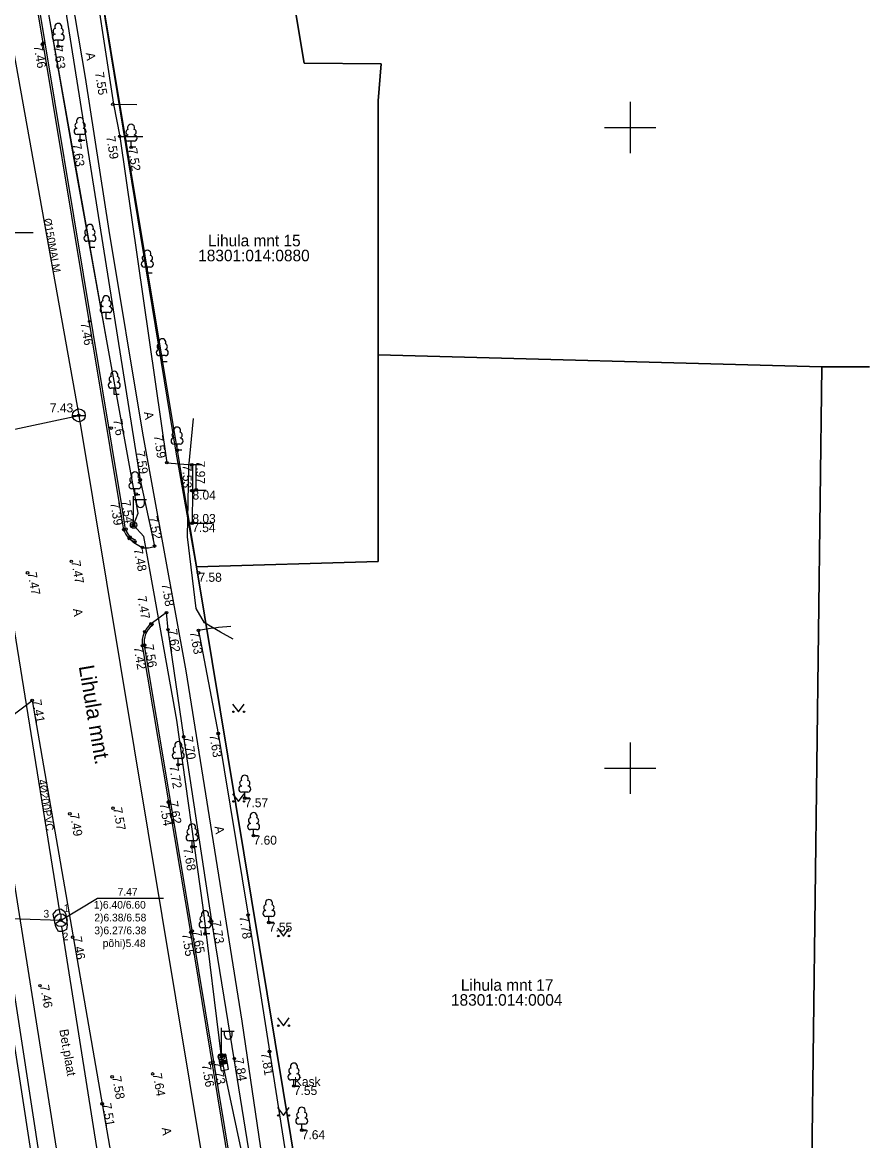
# Model space of a CAD drawing. Extents: x 473307 to 473719, y 6532843 to 6533381.
# Drawn here: x 473652.6 to 473718.7, y 6532970.9 to 6533058.2 of the extents above; entities that cross this region are included whole.
import ezdxf

# ---------------------------------------------------------------- set-up
doc = ezdxf.new("R2010")
doc.units = 0
for name, color, linetype in [('Default', 7, 'Continuous'), ('ELRAJATISMP', 7, 'Continuous'), ('HALJASTUS', 7, 'Continuous'), ('HOONEDET', 7, 'Continuous'), ('KORGUS', 7, 'Continuous'), ('KPKAABEL', 7, 'Continuous'), ('MPKAABEL', 7, 'Continuous'), ('PIIR', 7, 'Continuous'), ('POST', 7, 'Continuous'), ('PUU', 7, 'Continuous'), ('SIKAEV', 7, 'Continuous'), ('SIKAEV_NR', 7, 'Continuous'), ('SITRASS', 7, 'Continuous'), ('SITRASS_TEKST', 7, 'Continuous'), ('TEE', 7, 'Continuous'), ('TRUUP', 7, 'Continuous'), ('TTRASS', 7, 'Continuous'), ('VKAEV', 7, 'Continuous'), ('VORK', 7, 'Continuous'), ('VTRASS', 7, 'Continuous')]:
    doc.layers.add(name, color=color, linetype=linetype)

# ---------------------------------------------------------------- blocks, each defined once
blk = doc.blocks.new('eljk')
at = {"layer": 'Default'}
for p, q in [((1.19, 0.6), (-1.19, 0.6)), ((-1.19, 0.6), (-1.19, -0.6)), ((-0.27, 0.6), (-0.27, -0.6)), ((0.27, 0.57), (-0.27, 0.57)), ((0.27, 0.54), (-0.27, 0.54)), ((0.27, 0.51), (-0.27, 0.51)), ((0.27, 0.49), (-0.27, 0.49)), ((0.27, 0.46), (-0.27, 0.46)), ((0.27, 0.43), (-0.27, 0.43)), ((0.27, 0.4), (-0.27, 0.4)), ((0.27, 0.37), (-0.27, 0.37)), ((0.27, 0.34), (-0.27, 0.34)), ((0.27, 0.31), (-0.27, 0.31)), ((0.27, 0.28), (-0.27, 0.28)), ((0.27, 0.25), (-0.27, 0.25)), ((0.27, 0.22), (-0.27, 0.22)), ((0.27, 0.2), (-0.27, 0.2)), ((0.27, 0.17), (-0.27, 0.17)), ((0.27, 0.14), (-0.27, 0.14)), ((0.27, 0.11), (-0.27, 0.11)), ((0.27, 0.09), (-0.27, 0.09)), ((0.27, 0.06), (-0.27, 0.06)), ((0.27, 0.03), (-0.27, 0.03)), ((0.27, 0.6), (0.27, -0.6)), ((1.19, -0.6), (1.19, 0.6)), ((-1.19, -0.6), (1.19, -0.6)), ((0.27, 0), (-0.27, 0)), ((0.27, -0.03), (-0.27, -0.03)), ((0.27, -0.06), (-0.27, -0.06)), ((0.27, -0.09), (-0.27, -0.09)), ((0.27, -0.12), (-0.27, -0.12)), ((0.27, -0.14), (-0.27, -0.14)), ((0.27, -0.17), (-0.27, -0.17)), ((0.27, -0.2), (-0.27, -0.2)), ((0.27, -0.23), (-0.27, -0.23)), ((0.27, -0.26), (-0.27, -0.26)), ((0.27, -0.29), (-0.27, -0.29)), ((0.27, -0.32), (-0.27, -0.32)), ((0.27, -0.35), (-0.27, -0.35)), ((0.27, -0.37), (-0.27, -0.37)), ((0.27, -0.4), (-0.27, -0.4)), ((0.27, -0.43), (-0.27, -0.43)), ((0.27, -0.46), (-0.27, -0.46)), ((0.27, -0.48), (-0.27, -0.48)), ((0.27, -0.51), (-0.27, -0.51)), ((0.27, -0.54), (-0.27, -0.54)), ((0.27, -0.57), (-0.27, -0.57))]:
    blk.add_line(p, q, dxfattribs=at)
blk = doc.blocks.new('LEHTP1')
at = {"layer": 'Default'}
for p, q in [((0.48, 0.95), (-0.48, 0.95)), ((0, 0), (0, 0.95)), ((0.76, 0), (0, 0))]:
    blk.add_line(p, q, dxfattribs=at)
for centre, radius, start, end in [((0, 3.04), 0.554, 332.5799, 207.4201), ((-0.47, 1.42), 0.475, 90.0016, 269.3953), ((-0.34, 2.35), 0.465, 109.0217, 253.1415), ((0.34, 2.35), 0.465, 286.8508, 70.9859), ((0.47, 1.42), 0.475, 270.6047, 89.9984)]:
    blk.add_arc(centre, radius, start, end, dxfattribs=at)
blk = doc.blocks.new('VEKAEV')
at = {"layer": 'Default'}
blk.add_line((-1, 0), (1, 0), dxfattribs=at)
blk.add_circle((0, 0), 1, dxfattribs=at)
blk = doc.blocks.new('MEPOST')
at = {"layer": 'Default'}
blk.add_circle((0, 0), 0.5, dxfattribs=at)
for start, end in [(0, 180), (180, 0)]:
    blk.add_arc((0, 0), 0.25, start, end, dxfattribs=at)
blk = doc.blocks.new('VAPOST')
at = {"layer": 'Default'}
for p, q in [((0, 0.5), (0, 4.5)), ((0, 4), (2, 4)), ((0.45, 3.36), (0.45, 4)), ((1.68, 3.36), (1.68, 4))]:
    blk.add_line(p, q, dxfattribs=at)
blk.add_arc((1.07, 3.36), 0.613, 180, 0, dxfattribs=at)
blk = doc.blocks.new('SIKAEV')
at = {"layer": 'Default'}
for p, q in [((0, 0), (-0.83, -0.55)), ((0, 1), (0, 0)), ((0, 0), (0.83, -0.55))]:
    blk.add_line(p, q, dxfattribs=at)
blk.add_circle((0, 0), 1, dxfattribs=at)
blk = doc.blocks.new('MURU')
at = {"layer": 'Default'}
for p, q in [((-0.93, 1.21), (0, 0)), ((0, 0), (0.89, 1.21))]:
    blk.add_line(p, q, dxfattribs=at)
for centre in [(-0.8, 0), (0.86, 0)]:
    blk.add_circle(centre, 0.11, dxfattribs=at)
blk = doc.blocks.new('VKORIS')
at = {"layer": 'Default'}
for p, q in [((0, 4), (0, -4)), ((-4, 0), (4, 0))]:
    blk.add_line(p, q, dxfattribs=at)

msp = doc.modelspace()

# ---------------------------------------------------------------- linework, layer by layer
at = {"layer": 'HOONEDET'}
for points in [[(473666.557, 6533023.671), (473665.835, 6533023.673), (473665.828, 6533021.67)], [(473666.12, 6533021.669), (473666.128, 6533023.672)], [(473666.917, 6533021.667), (473665.828, 6533021.67), (473665.818, 6533019.121), (473667.375, 6533019.118)]]:
    msp.add_lwpolyline(points, dxfattribs=at)
at = {"layer": 'KORGUS'}
for centre, radius in [((473654.118, 6533056.493), 0.1), ((473654.187, 6533056.576), 0.1), ((473655.356, 6533056.333), 0.1), ((473659.616, 6533051.815), 0.1), ((473657.066, 6533048.983), 0.1), ((473660.157, 6533049.307), 0.1), ((473661.045, 6533048.46), 0.1), ((473657.781, 6533034.866), 0.07), ((473656.972, 6533027.535), 0.1), ((473659.496, 6533026.542), 0.1), ((473664.639, 6533024.819), 0.1), ((473663.835, 6533023.839), 0.1), ((473665.786, 6533023.673), 0.1), ((473661.758, 6533022.504), 0.1), ((473665.77, 6533021.655), 0.1), ((473665.84, 6533021.664), 0.1), ((473666.12, 6533021.73), 0.1), ((473661.444, 6533021.382), 0.1), ((473661.087, 6533018.925), 0.1), ((473665.818, 6533019.121), 0.1), ((473665.831, 6533019.14), 0.1), ((473660.473, 6533018.606), 0.1), ((473660.645, 6533018.657), 0.1), ((473660.908, 6533017.919), 0.1), ((473660.964, 6533018.027), 0.1), ((473661.352, 6533017.673), 0.1), ((473661.924, 6533017.228), 0.1), ((473662.882, 6533017.332), 0.1), ((473656.378, 6533016.138), 0.1), ((473652.969, 6533015.244), 0.1), ((473666.305, 6533015.245), 0.1), ((473663.808, 6533012.138), 0.1), ((473662.618, 6533011.26), 0.1), ((473662.676, 6533011.22), 0.1), ((473662.103, 6533010.65), 0.1), ((473663.93, 6533010.804), 0.1), ((473666.309, 6533010.756), 0.1), ((473661.937, 6533009.56), 0.1), ((473662.091, 6533009.601), 0.1), ((473653.33, 6533005.292), 0.1), ((473665.153, 6533002.439), 0.1), ((473667.851, 6533002.7), 0.1), ((473664.724, 6533000.272), 0.1), ((473663.955, 6532997.35), 0.1), ((473663.99, 6532997.38), 0.1), ((473669.923, 6532997.654), 0.1), ((473656.261, 6532996.431), 0.1), ((473659.637, 6532996.876), 0.1), ((473670.607, 6532994.729), 0.1), ((473665.809, 6532993.859), 0.1), ((473670.179, 6532988.536), 0.1), ((473655.555, 6532988.13), 0.1), ((473667.339, 6532988.049), 0.1), ((473671.801, 6532987.949), 0.1), ((473656.485, 6532986.805), 0.1), ((473665.698, 6532987.183), 0.1), ((473665.828, 6532987.292), 0.1), ((473666.826, 6532987.07), 0.1), ((473653.934, 6532983.024), 0.1), ((473667.424, 6532977.054), 0.1), ((473668.179, 6532977.534), 0.1), ((473669.104, 6532977.32), 0.1), ((473671.855, 6532977.881), 0.1), ((473667.246, 6532976.969), 0.1), ((473668.274, 6532977.007), 0.1), ((473659.562, 6532975.903), 0.1), ((473662.73, 6532976.134), 0.1), ((473673.755, 6532975.19), 0.1), ((473658.788, 6532973.8), 0.1), ((473674.37, 6532971.741), 0.1)]:
    msp.add_circle(centre, radius, dxfattribs=at)
at = {"layer": 'KPKAABEL'}
msp.add_lwpolyline([(473649.739, 6533117.241), (473649.707, 6533117.221), (473648.432, 6533115.3), (473647.869, 6533113.278), (473648.075, 6533109.541), (473648.364, 6533107.52), (473657.47, 6533053.904), (473659.301, 6533041.96), (473661.926, 6533026.149), (473665.326, 6533007.59), (473669.701, 6532980.256), (473673.645, 6532953.34), (473675.589, 6532943.911), (473677.672, 6532929.684), (473678.438, 6532923.998), (473681.198, 6532909.6), (473682.835, 6532903.795)], dxfattribs=at)
at = {"layer": 'MPKAABEL'}
for points in [[(473661.242, 6533018.973), (473661.609, 6533019.907), (473659.144, 6533033.364), (473656.715, 6533047.105), (473654.534, 6533059.446)], [(473674.649, 6532937.979), (473672.733, 6532950.348), (473670.825, 6532964.639), (473668.105, 6532977.477), (473666.684, 6532989.112), (473664.607, 6533003.741), (473662.829, 6533013.752), (473662.029, 6533018.09), (473661.242, 6533018.973), (473661.609, 6533019.907), (473659.144, 6533033.364), (473656.7, 6533046.917), (473654.534, 6533059.446)], [(473661.242, 6533018.973), (473661.609, 6533019.907), (473659.144, 6533033.364), (473656.715, 6533047.105), (473654.534, 6533059.446)], [(473668.105, 6532977.477), (473666.684, 6532989.112), (473664.607, 6533003.741), (473662.829, 6533013.752), (473662.029, 6533018.09), (473661.242, 6533018.973)], [(473674.649, 6532937.979), (473672.733, 6532950.348), (473670.825, 6532964.639), (473668.105, 6532977.477)]]:
    msp.add_lwpolyline(points, dxfattribs=at)
at = {"layer": 'PIIR'}
for points in [[(473609.342, 6533380.885), (473610.48, 6533371.09), (473616.72, 6533301.5), (473621.56, 6533285.32), (473637.37, 6533201.6), (473653.19, 6533109.36), (473652.55, 6533109.39), (473658.35, 6533068.44), (473658.1, 6533064.14), (473666.14, 6533015.71), (473666.15, 6533015.71), (473680.29, 6532930.36), (473685.16, 6532910.71), (473685.75, 6532908.33), (473689.51, 6532885.44), (473695.16, 6532852.24), (473696.267, 6532845.502)], [(473718.698, 6533031.329), (473714.97, 6533031.33), (473680.33, 6533032.25), (473680.33, 6533052.07), (473680.58, 6533054.96), (473674.56, 6533055.03), (473672.91, 6533064.83), (473672.27, 6533069.03), (473671.21, 6533075.65), (473671.43, 6533109.41), (473685.37, 6533109.4), (473685.63, 6533125.3), (473718.698, 6533125.502)], [(473718.698, 6532940.608), (473713.8, 6532938.13), (473714.97, 6533031.33), (473718.698, 6533031.329)]]:
    msp.add_lwpolyline(points, dxfattribs=at)
for points in [[(473666.15, 6533015.71), (473664.56, 6533024.65), (473658.1, 6533064.14), (473672.91, 6533064.83), (473674.56, 6533055.03), (473680.58, 6533054.96), (473680.33, 6533052.07), (473680.33, 6533032.25), (473680.34, 6533021.8), (473680.34, 6533016.12)], [(473680.33, 6533032.25), (473714.97, 6533031.33), (473713.8, 6532938.13), (473680.29, 6532930.36), (473666.15, 6533015.71), (473680.34, 6533016.12), (473680.34, 6533021.8)]]:
    msp.add_lwpolyline(points, close=True, dxfattribs=at)
at = {"layer": 'SIKAEV_NR'}
for points in [[(473646.921, 6533043.269), (473648.12, 6533041.798), (473653.413, 6533041.798)], [(473655.549, 6532988.099), (473658.418, 6532989.852), (473663.573, 6532989.852)]]:
    msp.add_lwpolyline(points, dxfattribs=at)
at = {"layer": 'SITRASS'}
for points in [[(473646.684, 6533043.163), (473655.476, 6532988.623)], [(473669.002, 6533010.065), (473668.038, 6533010.606), (473666.773, 6533011.346), (473666.137, 6533012.448), (473665.442, 6533018.056), (473665.564, 6533023.509), (473665.906, 6533027.292)], [(473590.274, 6532983.589), (473593.199, 6532984.483), (473615.964, 6532989.523), (473632.286, 6532988.799), (473642.743, 6532988.547), (473655.555, 6532988.13)], [(473665.7, 6532924.051), (473655.633, 6532987.636)]]:
    msp.add_lwpolyline(points, dxfattribs=at)
msp.add_lwpolyline([(473655.39, 6532987.262), (473655.169, 6532987.614), (473654.967, 6532988.605), (473655.226, 6532988.926), (473655.565, 6532989.007), (473655.819, 6532988.838), (473655.961, 6532988.596), (473656.046, 6532987.766), (473655.992, 6532987.418), (473655.683, 6532987.258)], close=True, dxfattribs=at)
at = {"layer": 'TEE'}
for points in [[(473645.987, 6533105.859), (473646.268, 6533106.585), (473647.731, 6533106.765), (473647.962, 6533106.66), (473648.35, 6533105.953), (473651.475, 6533086.758), (473654.599, 6533067.563), (473661.758, 6533022.504), (473662.882, 6533017.332)], [(473660.473, 6533018.606), (473660.473, 6533018.606), (473660.165, 6533020.473), (473654.187, 6533056.576), (473650.122, 6533080.936), (473645.987, 6533105.859)], [(473660.62, 6533018.637), (473660.313, 6533020.498), (473654.335, 6533056.601), (473650.27, 6533080.961), (473646.135, 6533105.884)], [(473656.943, 6533070.175), (473657.324, 6533067.592), (473657.769, 6533064.232), (473659.673, 6533051.815), (473660.157, 6533049.307), (473663.835, 6533023.839), (473665.835, 6533023.673)], [(473659.677, 6533051.815), (473661.501, 6533051.8)], [(473660.157, 6533049.307), (473661.951, 6533049.293)], [(473677.012, 6532932.049), (473675.928, 6532937.949), (473674.792, 6532943.923), (473671.861, 6532960.185), (473669.104, 6532977.32), (473667.339, 6532988.049), (473665.153, 6533002.439), (473663.93, 6533010.804), (473663.808, 6533012.138), (473662.618, 6533011.26)], [(473666.309, 6533010.756), (473667.851, 6533002.7), (473670.179, 6532988.536), (473675.003, 6532957.858), (473677.674, 6532942.946), (473678.484, 6532938.206), (473679.013, 6532935.283), (473679.795, 6532930.652)], [(473675.267, 6532928.908), (473674.786, 6532932.077), (473674.646, 6532932.846), (473671.83, 6532949.898), (473670.208, 6532959.779), (473665.698, 6532987.183), (473661.937, 6533009.56)], [(473675.415, 6532928.93), (473674.934, 6532932.102), (473674.794, 6532932.872), (473671.978, 6532949.922), (473670.356, 6532959.804), (473665.846, 6532987.207), (473662.085, 6533009.585)], [(473651.595, 6533003.976), (473653.33, 6533005.292), (473660.688, 6532962.839), (473658.944, 6532963.287), (473658.413, 6532963.417)]]:
    msp.add_lwpolyline(points, dxfattribs=at)
for centre, radius, start, end in [((473661.764, 6533018.942), 1.334, 194.59014, 252.0187), ((473661.764, 6533018.942), 1.184, 194.91103, 252.0187), ((473663.64, 6533020.845), 4.004, 226.9642, 244.61835), ((473662.241, 6533018.769), 1.574, 258.35645, 294.02211), ((473663.663, 6533009.855), 1.751, 126.65876, 189.71978), ((473663.663, 6533009.855), 1.601, 126.65876, 189.72804), ((473671.893, 6532975.747), 35.451, 94.9684, 99.06168)]:
    msp.add_arc(centre, radius, start, end, dxfattribs=at)
at = {"layer": 'TRUUP'}
msp.add_lwpolyline([(473656.327, 6532963.442), (473649.904, 6533003.695)], dxfattribs=at)
at = {"layer": 'TTRASS'}
for points in [[(473670.739, 6532903.73), (473669.823, 6532910.623), (473662.59, 6532909.156), (473646.821, 6533011.679), (473633.537, 6533100.476), (473633.406, 6533101.178), (473632.559, 6533105.696), (473632.32, 6533106.603), (473631.402, 6533106.697), (473628.136, 6533106.491), (473627.343, 6533106.38), (473626.399, 6533106.377), (473626.238, 6533107.261), (473626.052, 6533109.168), (473625.777, 6533111.724), (473625.749, 6533112.421), (473625.73, 6533112.829)], [(473671.344, 6532903.733), (473670.333, 6532911.339), (473663.087, 6532909.869), (473647.414, 6533011.77), (473634.242, 6533098.966), (473634.072, 6533100.094), (473632.984, 6533106.198), (473632.738, 6533107.055), (473631.832, 6533107.173), (473627.702, 6533106.877), (473626.788, 6533106.911), (473626.656, 6533107.813), (473626.548, 6533108.653), (473626.413, 6533111.755), (473626.375, 6533112.253)]]:
    msp.add_lwpolyline(points, dxfattribs=at)
at = {"layer": 'VTRASS'}
for points in [[(473650.187, 6533065.267), (473656.972, 6533027.535), (473675.322, 6532917.037), (473677.26, 6532903.765)], [(473616.216, 6533018.84), (473656.972, 6533027.535)]]:
    msp.add_lwpolyline(points, dxfattribs=at)

# ---------------------------------------------------------------- block references
at = {"layer": 'ELRAJATISMP', "xscale": 0.5, "yscale": 0.5000000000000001, "rotation": -79.26041130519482}
msp.add_blockref('eljk', (473668.257, 6532977.027), dxfattribs=at)
at = {"layer": 'HALJASTUS', "xscale": 0.5, "yscale": 0.5}
for p in [(473669.438, 6533004.399), (473669.438, 6532997.399), (473672.938, 6532986.899), (473672.938, 6532979.899), (473672.938, 6532972.899)]:
    msp.add_blockref('MURU', p, dxfattribs=at)
at = {"layer": 'POST', "xscale": 0.5, "yscale": 0.5}
for name, p in [('VAPOST', (473661.242, 6533018.973)), ('MEPOST', (473661.242, 6533018.973)), ('VAPOST', (473668.105, 6532977.477)), ('MEPOST', (473668.105, 6532977.477))]:
    msp.add_blockref(name, p, dxfattribs=at)
at = {"layer": 'PUU', "xscale": 0.5, "yscale": 0.5}
for p in [(473655.356, 6533056.333), (473657.066, 6533048.983), (473661.045, 6533048.46), (473657.827, 6533040.646), (473662.316, 6533038.625), (473659.099, 6533035.079), (473663.477, 6533031.722), (473659.73, 6533029.174), (473664.639, 6533024.819), (473661.35, 6533021.324), (473664.724, 6533000.272), (473669.923, 6532997.654), (473670.607, 6532994.729), (473665.809, 6532993.859), (473671.801, 6532987.949), (473666.826, 6532987.07), (473673.755, 6532975.19), (473674.37, 6532971.741)]:
    msp.add_blockref('LEHTP1', p, dxfattribs=at)
at = {"layer": 'SIKAEV', "xscale": 0.5, "yscale": 0.5}
msp.add_blockref('SIKAEV', (473655.555, 6532988.13), dxfattribs=at)
at = {"layer": 'VKAEV', "xscale": 0.5, "yscale": 0.5}
msp.add_blockref('VEKAEV', (473656.972, 6533027.535), dxfattribs=at)
at = {"layer": 'VORK', "xscale": 0.5, "yscale": 0.5}
for p in [(473700, 6533050), (473700, 6533000)]:
    msp.add_blockref('VKORIS', p, dxfattribs=at)

# ---------------------------------------------------------------- texts
at = {"layer": 'KORGUS'}
for s, rotation, p in [('7.46', 280, (473653.428, 6533056.372)), ('7.63', 279.12804, (473654.963, 6533056.315)), ('7.55', 279.39266, (473658.215, 6533054.284)), ('7.63', 279.2502, (473656.447, 6533048.704)), ('7.59', 279.39266, (473659.101, 6533049.284)), ('7.52', 279.39266, (473660.813, 6533048.341)), ('7.46', 280, (473657.092, 6533034.745)), ('7.6', 279.2502, (473659.65, 6533027.196)), ('7.59', 278.21776, (473662.823, 6533025.949)), ('7.59', 279.02714, (473661.408, 6533024.71)), ('7.53', 269.78038, (473665.086, 6533023.676)), ('7.97', 269.78038, (473666.129, 6533023.996)), ('7.54', 279.37202, (473660.281, 6533020.861)), ('7.39', 279.37202, (473659.419, 6533020.695)), ('7.52', 282.26041, (473662.394, 6533019.579)), ('7.54', 359.86064, (473665.816, 6533018.421)), ('8.03', 359.86064, (473665.831, 6533019.14)), ('7.48', 281.43612, (473661.238, 6533017.089)), ('7.47', 280, (473656.378, 6533016.138)), ('7.47', 280, (473652.969, 6533015.244)), ('7.58', 280, (473663.415, 6533014.37)), ('7.47', 280, (473661.535, 6533013.371)), ('7.62', 278.3183, (473663.93, 6533010.804)), ('7.63', 280.83688, (473665.622, 6533010.624)), ('7.42', 279.53939, (473661.247, 6533009.444)), ('7.56', 279.53939, (473662.091, 6533009.601)), ('7.41', 279.84563, (473653.33, 6533005.291)), ('7.70', 278.63761, (473665.153, 6533002.439)), ('7.63', 279.33407, (473667.16, 6533002.587)), ('7.72', 279.53939, (473664.033, 6533000.156)), ('7.54', 280, (473663.266, 6532997.228)), ('7.62', 280, (473663.99, 6532997.38)), ('7.49', 280, (473656.261, 6532996.431)), ('7.57', 280, (473659.637, 6532996.876)), ('7.68', 280, (473665.119, 6532993.737)), ('7.78', 278.93562, (473669.488, 6532988.427)), ('7.73', 279.34421, (473667.339, 6532988.049)), ('7.46', 280, (473656.485, 6532986.805)), ('7.55', 279.34583, (473665.007, 6532987.069)), ('7.65', 279.34583, (473665.828, 6532987.292)), ('7.46', 280, (473653.934, 6532983.024)), ('7.73', 280, (473667.424, 6532977.054)), ('7.84', 280, (473669.104, 6532977.32)), ('7.81', 280, (473671.165, 6532977.759)), ('7.56', 280, (473666.557, 6532976.847)), ('7.58', 280, (473659.562, 6532975.903)), ('7.64', 280, (473662.73, 6532976.134)), ('7.51', 280, (473658.788, 6532973.8))]:
    msp.add_text(s, height=0.7, rotation=rotation, dxfattribs=at).set_placement(p)
for s, p in [('7.43', (473654.705, 6533027.769)), ('8.04', (473665.84, 6533020.964)), ('7.58', (473666.305, 6533014.545)), ('7.57', (473669.923, 6532996.954)), ('7.60', (473670.607, 6532994.029)), ('7.55', (473671.801, 6532987.249)), ('7.55', (473673.755, 6532974.49)), ('7.64', (473674.37, 6532971.041))]:
    msp.add_text(s, height=0.7, dxfattribs=at).set_placement(p)
at = {"layer": 'PIIR'}
for s, p in [('Lihula mnt 15', (473667.056, 6533040.727)), ('18301:014:0880', (473666.286, 6533039.562)), ('Lihula mnt 17', (473686.787, 6532982.625)), ('18301:014:0004', (473686.017, 6532981.46))]:
    msp.add_text(s, height=0.9, dxfattribs=at).set_placement(p)
at = {"layer": 'PUU'}
msp.add_text('Kask', height=0.7, dxfattribs=at).set_placement((473673.755, 6532975.19))
at = {"layer": 'SIKAEV_NR'}
for s, p in [('7.47', (473659.996, 6532990.052)), ('1', (473655.78, 6532988.766)), ('1)6.40/6.60', (473658.134, 6532989.036)), ('3', (473654.207, 6532988.338)), ('2)6.38/6.58', (473658.176, 6532988.036)), ('3)6.27/6.38', (473658.176, 6532987.036)), ('2', (473655.703, 6532986.562)), ('põhi)5.48', (473658.834, 6532986.036))]:
    msp.add_text(s, height=0.6, dxfattribs=at).set_placement(p)
at = {"layer": 'SITRASS_TEKST'}
msp.add_text('4%%C200PVC', height=0.6, rotation=279.15701, dxfattribs=at).set_placement((473653.791, 6532999.077))
at = {"layer": 'TEE'}
for s, height, rotation, p in [('A', 0.7, 279.44315, (473657.5, 6533055.807)), ('A', 0.7, 279.44315, (473662.047, 6533027.776)), ('A', 0.7, 277.89795, (473656.512, 6533012.42)), ('Lihula mnt.', 1.2, 279.56182, (473656.954, 6533007.946)), ('A', 0.7, 278.93562, (473667.557, 6532995.435)), ('Bet.plaat', 0.7, 279.82046, (473655.443, 6532979.569)), ('A', 0.7, 277.88702, (473663.437, 6532971.922))]:
    msp.add_text(s, height=height, rotation=rotation, dxfattribs=at).set_placement(p)
at = {"layer": 'VTRASS'}
msp.add_text('%%c150MALM', height=0.6, rotation=280.07112, dxfattribs=at).set_placement((473654.222, 6533042.858))

doc.saveas('drawing.dxf')
